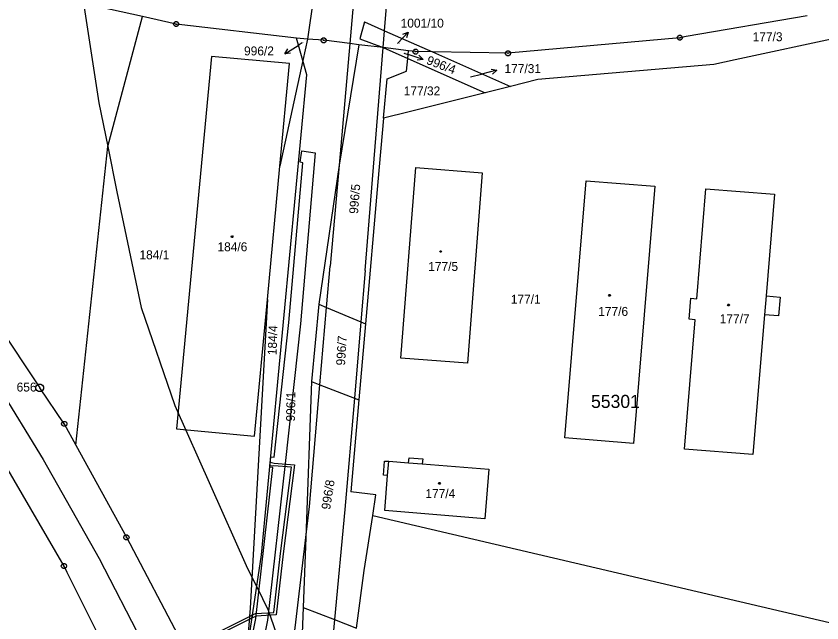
# Model space of a CAD drawing. Extents: x -755359 to -754474, y -1162585 to -1161655.
# Drawn here: x -755164.4 to -755011, y -1162361.4 to -1162245.9 of the extents above; entities that cross this region are included whole.
import ezdxf

# ---------------------------------------------------------------- set-up
doc = ezdxf.new("R2010")
doc.units = 0
for name, color, linetype in [('Vrstva 1', 7, 'Continuous'), ('Vrstva 11', 7, 'Continuous'), ('Vrstva 12', 7, 'Continuous'), ('Vrstva 13', 7, 'Continuous'), ('Vrstva 2', 7, 'Continuous'), ('Vrstva 4', 7, 'Continuous'), ('Vrstva 5', 7, 'Continuous'), ('Vrstva 6', 7, 'Continuous'), ('Vrstva 7', 7, 'Continuous'), ('Vrstva 8', 7, 'Continuous')]:
    doc.layers.add(name, color=color, linetype=linetype)

msp = doc.modelspace()

# ---------------------------------------------------------------- linework, layer by layer
at = {"layer": 'Vrstva 1'}
for p, q in [((-755106.85, -1162236.16), (-755108.91, -1162250.29)), ((-755140.31, -1162246.01), (-755156.59, -1162242.36)), ((-755146.94, -1162270.72), (-755140.31, -1162246.01)), ((-755133.9, -1162247.44), (-755140.31, -1162246.01)), ((-755013.79, -1162245.86), (-755036.82, -1162249.84)), ((-755110.99, -1162250.12), (-755133.9, -1162247.44)), ((-755098.08, -1162247.03), (-755098.92, -1162250.25)), ((-755098.08, -1162247.03), (-755094.25, -1162248.72)), ((-755094.25, -1162248.72), (-755085.12, -1162252.75)), ((-755038.01, -1162250.05), (-755070.73, -1162253.01)), ((-755036.82, -1162249.84), (-755038.01, -1162250.05)), ((-755006.22, -1162249.72), (-755027.5, -1162254.28)), ((-755109.79, -1162254.37), (-755110.99, -1162250.12)), ((-755108.91, -1162250.29), (-755110.99, -1162250.12)), ((-755108.91, -1162250.29), (-755109.79, -1162254.37)), ((-755105.8, -1162250.54), (-755108.91, -1162250.29)), ((-755100.83, -1162251.16), (-755105.8, -1162250.54)), ((-755099.1, -1162251.37), (-755102.88, -1162274.28)), ((-755099.1, -1162251.37), (-755100.83, -1162251.16)), ((-755094.51, -1162251.93), (-755099.1, -1162251.37)), ((-755098.92, -1162250.25), (-755094.51, -1162251.93)), ((-755094.51, -1162251.93), (-755089.82, -1162254)), ((-755089.68, -1162252.52), (-755094.51, -1162251.93)), ((-755089.82, -1162254), (-755089.68, -1162252.52)), ((-755088.33, -1162252.69), (-755089.68, -1162252.52)), ((-755085.12, -1162252.75), (-755088.33, -1162252.69)), ((-755085.12, -1162252.75), (-755070.25, -1162259.31)), ((-755070.73, -1162253.01), (-755085.12, -1162252.75)), ((-755127.15, -1162253.59), (-755133.83, -1162324.47)), ((-755112.31, -1162254.97), (-755127.15, -1162253.59)), ((-755109.79, -1162254.37), (-755114.15, -1162274.5)), ((-755109.03, -1162257.08), (-755109.79, -1162254.37)), ((-755090.06, -1162256.44), (-755089.82, -1162254)), ((-755089.82, -1162254), (-755075.07, -1162260.52)), ((-755027.5, -1162254.28), (-755031.53, -1162255.15)), ((-755114.15, -1162274.5), (-755112.31, -1162254.97)), ((-755031.53, -1162255.15), (-755065.07, -1162258.01)), ((-755117.64, -1162348.46), (-755109.03, -1162257.08)), ((-755093.76, -1162257.89), (-755090.06, -1162256.44)), ((-755094.42, -1162265.37), (-755093.76, -1162257.89)), ((-755065.07, -1162258.01), (-755070.25, -1162259.31)), ((-755075.07, -1162260.52), (-755089.54, -1162264.15)), ((-755070.25, -1162259.31), (-755075.07, -1162260.52)), ((-755094.42, -1162265.37), (-755095.48, -1162277.47)), ((-755089.54, -1162264.15), (-755094.42, -1162265.37)), ((-755152.98, -1162327.62), (-755146.94, -1162270.72)), ((-755116.54, -1162299.9), (-755114.15, -1162274.5)), ((-755102.88, -1162274.28), (-755106.74, -1162300.78)), ((-755091.1, -1162311.01), (-755088.26, -1162274.77)), ((-755088.26, -1162274.77), (-755075.65, -1162275.78)), ((-755075.65, -1162275.78), (-755078.45, -1162312.01)), ((-755095.48, -1162277.47), (-755097.85, -1162304.49)), ((-755059.91, -1162326.2), (-755055.83, -1162277.26)), ((-755055.83, -1162277.26), (-755042.74, -1162278.32)), ((-755042.74, -1162278.32), (-755046.82, -1162327.29)), ((-755034.79, -1162299.73), (-755033.03, -1162278.8)), ((-755033.03, -1162278.8), (-755019.99, -1162279.84)), ((-755019.99, -1162279.84), (-755021.59, -1162299.2)), ((-755179.66, -1162287.01), (-755159.89, -1162316.68)), ((-755116.54, -1162299.9), (-755119.82, -1162358.61)), ((-755118.98, -1162325.91), (-755116.54, -1162299.9)), ((-755036.21, -1162303.63), (-755035.89, -1162299.63)), ((-755035.89, -1162299.63), (-755034.79, -1162299.73)), ((-755021.59, -1162299.2), (-755018.93, -1162299.42)), ((-755018.93, -1162299.42), (-755019.23, -1162303)), ((-755106.74, -1162300.78), (-755108.15, -1162315.51)), ((-755106.74, -1162300.78), (-755105.27, -1162301.39)), ((-755105.27, -1162301.39), (-755098.74, -1162304.12)), ((-755037.14, -1162328.37), (-755035.12, -1162303.75)), ((-755035.12, -1162303.75), (-755036.21, -1162303.63)), ((-755021.89, -1162302.78), (-755024.1, -1162329.37)), ((-755019.23, -1162303), (-755021.89, -1162302.78)), ((-755097.85, -1162304.49), (-755099.13, -1162318.97)), ((-755098.74, -1162304.12), (-755097.85, -1162304.49)), ((-755078.45, -1162312.01), (-755091.1, -1162311.01)), ((-755108.15, -1162315.51), (-755109.24, -1162345.2)), ((-755108.15, -1162315.51), (-755106.54, -1162316.13)), ((-755155.21, -1162323.55), (-755159.89, -1162316.68)), ((-755106.54, -1162316.13), (-755099.98, -1162318.64)), ((-755099.13, -1162318.97), (-755100.67, -1162336.51)), ((-755099.98, -1162318.64), (-755099.13, -1162318.97)), ((-755155.21, -1162323.55), (-755152.98, -1162327.62)), ((-755133.83, -1162324.47), (-755118.98, -1162325.91)), ((-755046.82, -1162327.29), (-755059.91, -1162326.2)), ((-755155.26, -1162350.62), (-755168.69, -1162327.53)), ((-755152.98, -1162327.62), (-755143.37, -1162345.14)), ((-755024.1, -1162329.37), (-755037.14, -1162328.37)), ((-755094.46, -1162333.32), (-755094.24, -1162330.64)), ((-755094.24, -1162330.64), (-755093.41, -1162330.66)), ((-755093.41, -1162330.66), (-755089.64, -1162330.96)), ((-755089.64, -1162330.96), (-755089.57, -1162330)), ((-755089.57, -1162330), (-755086.96, -1162330.22)), ((-755086.96, -1162330.22), (-755087.04, -1162331.17)), ((-755087.04, -1162331.17), (-755074.37, -1162332.18)), ((-755074.37, -1162332.18), (-755075.13, -1162341.61)), ((-755093.64, -1162333.39), (-755094.46, -1162333.32)), ((-755094.19, -1162340.03), (-755093.64, -1162333.39)), ((-755095.88, -1162337.08), (-755100.67, -1162336.51)), ((-755096.49, -1162341), (-755095.88, -1162337.08)), ((-755075.13, -1162341.61), (-755094.19, -1162340.03)), ((-755098.12, -1162351.47), (-755096.49, -1162341)), ((-755096.49, -1162341), (-755007.12, -1162361.91)), ((-755143.37, -1162345.14), (-755132.01, -1162366.71)), ((-755109.24, -1162345.2), (-755109.73, -1162358.47)), ((-755120.58, -1162367.79), (-755117.64, -1162348.46)), ((-755154.66, -1162351.82), (-755155.26, -1162350.62)), ((-755141.68, -1162377.77), (-755154.66, -1162351.82)), ((-755099.55, -1162362.44), (-755098.12, -1162351.47)), ((-755119.82, -1162358.61), (-755120.58, -1162367.79)), ((-755109.73, -1162358.47), (-755110.28, -1162371.41)), ((-755109.73, -1162358.47), (-755103.73, -1162360.81)), ((-755103.73, -1162360.81), (-755099.55, -1162362.44))]:
    msp.add_line(p, q, dxfattribs=at)
at = {"layer": 'Vrstva 11'}
for p, q in [((-755151.54, -1162243.49), (-755148.61, -1162262.46)), ((-755148.61, -1162262.46), (-755146.94, -1162270.77)), ((-755146.94, -1162270.77), (-755145.22, -1162279.39)), ((-755145.22, -1162279.39), (-755140.55, -1162301.4)), ((-755140.55, -1162301.4), (-755134.18, -1162320.03)), ((-755134.18, -1162320.03), (-755120.6, -1162350.51)), ((-755120.6, -1162350.51), (-755119.49, -1162352.72)), ((-755119.49, -1162352.72), (-755118.57, -1162354.56)), ((-755118.57, -1162354.56), (-755116.36, -1162358.98)), ((-755116.36, -1162358.98), (-755110.69, -1162375.3))]:
    msp.add_line(p, q, dxfattribs=at)
at = {"layer": 'Vrstva 12'}
for p, q in [((-755127.15, -1162253.59), (-755133.83, -1162324.47)), ((-755112.31, -1162254.97), (-755127.15, -1162253.59)), ((-755114.15, -1162274.5), (-755112.31, -1162254.97)), ((-755116.54, -1162299.9), (-755114.15, -1162274.5)), ((-755091.1, -1162311.01), (-755088.26, -1162274.77)), ((-755088.26, -1162274.77), (-755075.65, -1162275.78)), ((-755075.65, -1162275.78), (-755078.45, -1162312.01)), ((-755059.91, -1162326.2), (-755055.83, -1162277.26)), ((-755055.83, -1162277.26), (-755042.74, -1162278.32)), ((-755042.74, -1162278.32), (-755046.82, -1162327.29)), ((-755034.79, -1162299.73), (-755033.03, -1162278.8)), ((-755033.03, -1162278.8), (-755019.99, -1162279.84)), ((-755019.99, -1162279.84), (-755021.59, -1162299.2)), ((-755118.98, -1162325.91), (-755116.54, -1162299.9)), ((-755036.21, -1162303.63), (-755035.89, -1162299.63)), ((-755035.89, -1162299.63), (-755034.79, -1162299.73)), ((-755021.59, -1162299.2), (-755021.89, -1162302.78)), ((-755037.14, -1162328.37), (-755035.12, -1162303.75)), ((-755035.12, -1162303.75), (-755036.21, -1162303.63)), ((-755021.89, -1162302.78), (-755024.1, -1162329.37)), ((-755078.45, -1162312.01), (-755091.1, -1162311.01)), ((-755133.83, -1162324.47), (-755118.98, -1162325.91)), ((-755046.82, -1162327.29), (-755059.91, -1162326.2)), ((-755024.1, -1162329.37), (-755037.14, -1162328.37)), ((-755093.64, -1162333.39), (-755093.41, -1162330.66)), ((-755093.41, -1162330.66), (-755089.64, -1162330.96)), ((-755089.64, -1162330.96), (-755087.04, -1162331.17)), ((-755087.04, -1162331.17), (-755074.37, -1162332.18)), ((-755074.37, -1162332.18), (-755075.13, -1162341.61)), ((-755094.19, -1162340.03), (-755093.64, -1162333.39)), ((-755075.13, -1162341.61), (-755094.19, -1162340.03))]:
    msp.add_line(p, q, dxfattribs=at)
at = {"layer": 'Vrstva 13'}
for p, q in [((-755110.32, -1162273.75), (-755109.97, -1162271.56)), ((-755107.42, -1162271.97), (-755110.26, -1162304.5)), ((-755109.97, -1162271.56), (-755107.42, -1162271.97)), ((-755112.46, -1162304.28), (-755109.82, -1162273.83)), ((-755109.82, -1162273.83), (-755110.32, -1162273.75)), ((-755115.25, -1162329.88), (-755112.46, -1162304.28)), ((-755110.26, -1162304.5), (-755113.15, -1162331.11)), ((-755116.07, -1162331.8), (-755115.88, -1162329.81)), ((-755115.88, -1162329.81), (-755115.25, -1162329.88)), ((-755113.15, -1162331.11), (-755116.54, -1162360.94)), ((-755116.05, -1162331.62), (-755115.98, -1162330.82)), ((-755115.98, -1162330.82), (-755115.27, -1162331.04)), ((-755115.27, -1162331.04), (-755111.39, -1162331.33)), ((-755111.39, -1162331.33), (-755113.55, -1162348.28)), ((-755118.74, -1162360.6), (-755115.47, -1162331.87)), ((-755115.47, -1162331.87), (-755116.07, -1162331.8)), ((-755115.31, -1162331.54), (-755116.05, -1162331.62)), ((-755111.95, -1162331.79), (-755115.31, -1162331.54)), ((-755114.05, -1162348.22), (-755111.95, -1162331.79)), ((-755115.31, -1162359.44), (-755114.05, -1162348.22)), ((-755113.55, -1162348.28), (-755114.87, -1162359.92)), ((-755132.22, -1162366.32), (-755119.95, -1162360.2)), ((-755119.95, -1162360.2), (-755119.38, -1162359.92)), ((-755119.38, -1162359.92), (-755119.48, -1162360.53)), ((-755119.48, -1162360.53), (-755119.38, -1162359.92)), ((-755118.66, -1162360.13), (-755119.48, -1162360.53)), ((-755119.38, -1162359.92), (-755118.8, -1162359.63)), ((-755118.8, -1162359.63), (-755115.31, -1162359.44)), ((-755114.87, -1162359.92), (-755118.66, -1162360.13)), ((-755120, -1162360.79), (-755132.01, -1162366.71)), ((-755120.84, -1162370.97), (-755118.74, -1162360.6)), ((-755119.48, -1162360.53), (-755120, -1162360.79)), ((-755116.54, -1162360.94), (-755118.85, -1162372.47))]:
    msp.add_line(p, q, dxfattribs=at)
at = {"layer": 'Vrstva 4'}
for p, q in [((-755100.18, -1162243.88), (-755100.83, -1162251.16)), ((-755094.25, -1162248.72), (-755093.88, -1162244.12)), ((-755094.51, -1162251.93), (-755094.25, -1162248.72)), ((-755100.83, -1162251.16), (-755102.88, -1162274.28)), ((-755096.52, -1162277.02), (-755094.51, -1162251.93)), ((-755102.88, -1162274.28), (-755104.59, -1162293.54)), ((-755097.9, -1162294.33), (-755096.52, -1162277.02)), ((-755105.27, -1162301.39), (-755104.59, -1162293.54)), ((-755097.9, -1162294.33), (-755098.74, -1162304.12)), ((-755021.59, -1162299.2), (-755021.89, -1162302.78)), ((-755106.54, -1162316.13), (-755105.27, -1162301.39)), ((-755098.74, -1162304.12), (-755099.98, -1162318.64)), ((-755108.54, -1162339.27), (-755106.54, -1162316.13)), ((-755099.98, -1162318.64), (-755101.79, -1162339.87)), ((-755093.64, -1162333.39), (-755093.41, -1162330.66)), ((-755089.64, -1162330.96), (-755087.04, -1162331.17)), ((-755109.24, -1162345.2), (-755108.54, -1162339.27)), ((-755101.79, -1162339.87), (-755103.73, -1162360.81)), ((-755112.82, -1162375.43), (-755109.24, -1162345.2)), ((-755103.73, -1162360.81), (-755104.84, -1162372.89))]:
    msp.add_line(p, q, dxfattribs=at)
at = {"layer": 'Vrstva 5'}
for points in [[(-755123.16, -1162287.78), (-755123.07, -1162287.93), (-755123.16, -1162288.08), (-755123.34, -1162288.08), (-755123.43, -1162287.93), (-755123.34, -1162287.78)], [(-755083.45, -1162290.58), (-755083.36, -1162290.73), (-755083.45, -1162290.88), (-755083.63, -1162290.88), (-755083.72, -1162290.73), (-755083.63, -1162290.58)], [(-755051.3, -1162298.91), (-755051.21, -1162299.06), (-755051.3, -1162299.21), (-755051.48, -1162299.21), (-755051.57, -1162299.06), (-755051.48, -1162298.91)], [(-755028.64, -1162300.76), (-755028.55, -1162300.91), (-755028.64, -1162301.06), (-755028.82, -1162301.06), (-755028.91, -1162300.91), (-755028.82, -1162300.76)], [(-755083.7, -1162334.71), (-755083.61, -1162334.86), (-755083.7, -1162335.01), (-755083.88, -1162335.01), (-755083.97, -1162334.86), (-755083.88, -1162334.71)]]:
    msp.add_lwpolyline(points, close=True, dxfattribs=at)
at = {"layer": 'Vrstva 6'}
for p, q in [((-755170.6, -1162311.78), (-755159.25, -1162330.3)), ((-755159.25, -1162330.3), (-755148.58, -1162349.19)), ((-755148.58, -1162349.19), (-755138.6, -1162368.43))]:
    msp.add_line(p, q, dxfattribs=at)
at = {"layer": 'Vrstva 7'}
for p, q in [((-755089.725, -1162248.965), (-755091.77, -1162251.16)), ((-755113.245, -1162253.109), (-755110.7, -1162251.52)), ((-755109.93, -1162251.05), (-755110.7, -1162251.52)), ((-755091.78, -1162251.17), (-755091.77, -1162251.16)), ((-755090.57, -1162252.98), (-755089.76, -1162253.24)), ((-755086.907, -1162254.168), (-755089.76, -1162253.24)), ((-755077.87, -1162257.5), (-755075.75, -1162256.98)), ((-755072.839, -1162256.253), (-755075.75, -1162256.98))]:
    msp.add_line(p, q, dxfattribs=at)
for points in [[(-755090.772, -1162249.356), (-755089.725, -1162248.965), (-755090.041, -1162250.038)], [(-755112.132, -1162253.003), (-755113.245, -1162253.109), (-755112.661, -1162252.155)], [(-755087.703, -1162253.383), (-755086.907, -1162254.168), (-755088.013, -1162254.334)], [(-755073.931, -1162256.011), (-755072.839, -1162256.253), (-755073.688, -1162256.981)]]:
    msp.add_lwpolyline(points, dxfattribs=at)
at = {"layer": 'Vrstva 8'}
for p, q in [((-755134.02, -1162247.44), (-755133.78, -1162247.44)), ((-755038.13, -1162250.05), (-755037.89, -1162250.05)), ((-755105.92, -1162250.54), (-755105.68, -1162250.54)), ((-755088.45, -1162252.69), (-755088.21, -1162252.69)), ((-755070.85, -1162253.01), (-755070.61, -1162253.01)), ((-755159.94, -1162316.68), (-755159.84, -1162316.68)), ((-755155.33, -1162323.55), (-755155.09, -1162323.55)), ((-755143.49, -1162345.14), (-755143.25, -1162345.14)), ((-755155.38, -1162350.62), (-755155.14, -1162350.62))]:
    msp.add_line(p, q, dxfattribs=at)
for points in [[(-755133.75, -1162246.96), (-755133.5, -1162247.14), (-755133.4, -1162247.43), (-755133.5, -1162247.72), (-755133.75, -1162247.9), (-755134.06, -1162247.9), (-755134.31, -1162247.72), (-755134.41, -1162247.43), (-755134.31, -1162247.14), (-755134.06, -1162246.96)], [(-755105.65, -1162250.06), (-755105.4, -1162250.24), (-755105.3, -1162250.53), (-755105.4, -1162250.82), (-755105.65, -1162251), (-755105.96, -1162251), (-755106.21, -1162250.82), (-755106.31, -1162250.53), (-755106.21, -1162250.24), (-755105.96, -1162250.06)], [(-755037.86, -1162249.57), (-755037.61, -1162249.75), (-755037.51, -1162250.04), (-755037.61, -1162250.33), (-755037.86, -1162250.51), (-755038.17, -1162250.51), (-755038.42, -1162250.33), (-755038.52, -1162250.04), (-755038.42, -1162249.75), (-755038.17, -1162249.57)], [(-755088.18, -1162252.21), (-755087.93, -1162252.39), (-755087.83, -1162252.68), (-755087.93, -1162252.97), (-755088.18, -1162253.15), (-755088.49, -1162253.15), (-755088.74, -1162252.97), (-755088.84, -1162252.68), (-755088.74, -1162252.39), (-755088.49, -1162252.21)], [(-755070.58, -1162252.53), (-755070.33, -1162252.71), (-755070.23, -1162253), (-755070.33, -1162253.29), (-755070.58, -1162253.47), (-755070.89, -1162253.47), (-755071.14, -1162253.29), (-755071.24, -1162253), (-755071.14, -1162252.71), (-755070.89, -1162252.53)], [(-755159.7, -1162315.96), (-755159.36, -1162316.15), (-755159.17, -1162316.49), (-755159.17, -1162316.88), (-755159.36, -1162317.22), (-755159.7, -1162317.41), (-755160.09, -1162317.41), (-755160.43, -1162317.22), (-755160.62, -1162316.88), (-755160.62, -1162316.49), (-755160.43, -1162316.15), (-755160.09, -1162315.96)], [(-755155.06, -1162323.07), (-755154.81, -1162323.25), (-755154.71, -1162323.54), (-755154.81, -1162323.83), (-755155.06, -1162324.01), (-755155.37, -1162324.01), (-755155.62, -1162323.83), (-755155.72, -1162323.54), (-755155.62, -1162323.25), (-755155.37, -1162323.07)], [(-755143.22, -1162344.66), (-755142.97, -1162344.84), (-755142.87, -1162345.13), (-755142.97, -1162345.42), (-755143.22, -1162345.6), (-755143.53, -1162345.6), (-755143.78, -1162345.42), (-755143.88, -1162345.13), (-755143.78, -1162344.84), (-755143.53, -1162344.66)], [(-755155.11, -1162350.14), (-755154.86, -1162350.32), (-755154.76, -1162350.61), (-755154.86, -1162350.9), (-755155.11, -1162351.08), (-755155.42, -1162351.08), (-755155.67, -1162350.9), (-755155.77, -1162350.61), (-755155.67, -1162350.32), (-755155.42, -1162350.14)]]:
    msp.add_lwpolyline(points, close=True, dxfattribs=at)

# ---------------------------------------------------------------- texts
at = {"layer": 'Vrstva 11'}
msp.add_text('55301', height=2.5, dxfattribs=at).set_placement((-755054.917, -1162320.52))
at = {"layer": 'Vrstva 2'}
for s, height, p in [('177/3', 1.7, (-755024.147, -1162250.71)), ('996/2', 0.1, (-755109.916, -1162251.05)), ('1001/10', 0.1, (-755091.757, -1162251.17)), ('996/4', 0.1, (-755090.556, -1162252.98)), ('177/31', 0.1, (-755077.847, -1162257.5)), ('177/32', 1.7, (-755090.577, -1162261.02)), ('184/6', 1.7, (-755126.042, -1162290.69)), ('184/1', 1.7, (-755140.897, -1162292.22)), ('177/5', 1.7, (-755085.917, -1162294.44)), ('177/1', 1.7, (-755070.197, -1162300.68)), ('177/6', 1.7, (-755053.547, -1162302.99)), ('177/7', 1.7, (-755030.417, -1162304.38)), ('177/4', 1.7, (-755086.457, -1162337.67))]:
    msp.add_text(s, height=height, dxfattribs=at).set_placement(p)
for s, rotation, p in [('996/5', 85.4853, (-755099.291, -1162283.633)), ('184/4', 88.17821, (-755114.788, -1162310.497)), ('996/7', 86.40204, (-755101.765, -1162312.483)), ('996/1', 89.09494, (-755111.286, -1162323.113)), ('996/8', 81.01623, (-755104.603, -1162339.946))]:
    msp.add_text(s, height=1.7, rotation=rotation, dxfattribs=at).set_placement(p)
at = {"layer": 'Vrstva 7'}
for s, p in [('1001/10', (-755091.167, -1162248.12)), ('996/2', (-755120.982, -1162253.41)), ('177/31', (-755071.397, -1162256.78))]:
    msp.add_text(s, height=1.7, dxfattribs=at).set_placement(p)
msp.add_text('996/4', height=1.7, rotation=339.01913, dxfattribs=at).set_placement((-755086.387, -1162254.992))
at = {"layer": 'Vrstva 8'}
msp.add_text('656', height=1.7, dxfattribs=at).set_placement((-755164.283, -1162317.39))

doc.saveas('drawing.dxf')
